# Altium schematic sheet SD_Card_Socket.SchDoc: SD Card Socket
size A4; DocumentNumber: 11; SheetNumber: 11; SheetTotal: 12
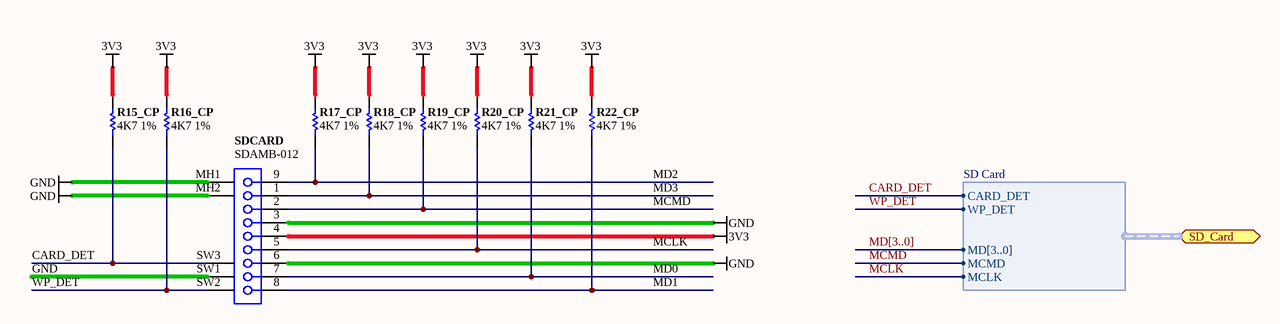
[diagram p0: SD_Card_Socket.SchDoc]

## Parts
R15_CP  4K7 1%  [RESC1005-STAR]
R16_CP  4K7 1%  [RESC1005-STAR]
R17_CP  4K7 1%  [RESC1005-STAR]
R18_CP  4K7 1%  [RESC1005-STAR]
R19_CP  4K7 1%  [RESC1005-STAR]
R20_CP  4K7 1%  [RESC1005-STAR]
R21_CP  4K7 1%  [RESC1005-STAR]
R22_CP  4K7 1%  [RESC1005-STAR]
SDCARD  SDAMB-012  [SDAMB-012]

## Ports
SD_Card (harness SD Card)

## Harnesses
SD Card: CARD_DET, WP_DET, MD[3..0], MCLK, MCMD

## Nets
3V3: R15_CP.2 R16_CP.2 R17_CP.2 R18_CP.2 R19_CP.2 R20_CP.2 R21_CP.2 R22_CP.2 SDCARD.4
GND: SDCARD.3 SDCARD.6 SDCARD.MH1 SDCARD.MH2 SDCARD.SW1
CARD_DET: R15_CP.1 SDCARD.SW3 ; port SD_Card.CARD_DET
MCLK: R20_CP.1 SDCARD.5 ; port SD_Card.MCLK
MCMD: R19_CP.1 SDCARD.2 ; port SD_Card.MCMD
MD0: R21_CP.1 SDCARD.7
MD1: R22_CP.1 SDCARD.8
MD2: R17_CP.1 SDCARD.9
MD3: R18_CP.1 SDCARD.1
WP_DET: R16_CP.1 SDCARD.SW2 ; port SD_Card.WP_DET

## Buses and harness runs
bus MD[3..0]

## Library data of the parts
R15_CP R16_CP R17_CP R18_CP R19_CP R20_CP R21_CP R22_CP = D-100-0088: Resistor, 4K7 1% 0402 (1005); Power Rating: 63 mW; Resistance: 4.7 K
SDCARD = D-300-0018: SDCARD Connector SDAMB-012; Connector type: Straight; Max Current: mA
